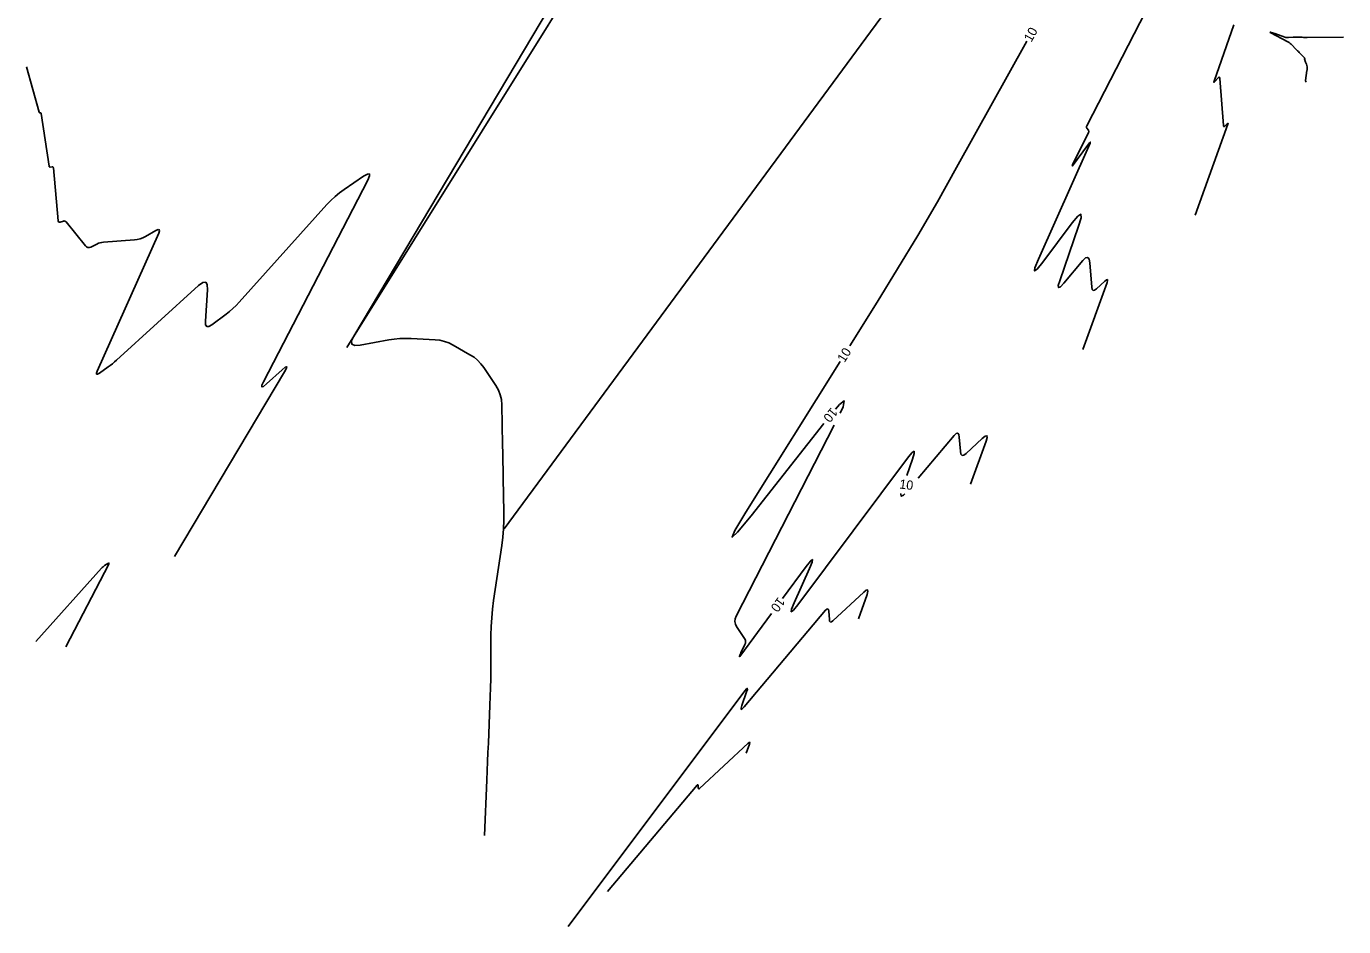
# Model space of a CAD drawing. Extents: x 1797789 to 1803805, y 249066 to 250293.
# Drawn here: x 1797789 to 1798641, y 249066 to 249649 of the extents above; entities that cross this region are included whole.
import ezdxf

# ---------------------------------------------------------------- set-up
doc = ezdxf.new("R2010")
doc.units = 0
doc.layers.add('33', color=7, linetype='Continuous')
doc.layers.add('34', color=7, linetype='Continuous')

msp = doc.modelspace()

# ---------------------------------------------------------------- linework, layer by layer
at = {"layer": '33'}
for points in [[(1798321.84, 249442.04), (1798339.44, 249470.2), (1798352.71, 249491.73), (1798365.7, 249513.42), (1798378.4, 249535.27), (1798390.83, 249557.29), (1798436.35, 249639.15)], [(1798304.84, 249391.7), (1798257.8, 249332.04), (1798249.05, 249321.35), (1798245.59, 249318.17), (1798247.41, 249322.51), (1798254.52, 249334.35), (1798315.48, 249431.87)], [(1798315.5, 249398.47), (1798317.39, 249402.46), (1798318.18, 249406.33), (1798314.99, 249404), (1798312.45, 249400.98)], [(1798271.07, 249268.72), (1798250.6, 249240.92), (1798250.45, 249240.74), (1798250.37, 249240.7), (1798250.36, 249240.79), (1798250.43, 249241.01), (1798250.82, 249242.17), (1798250.92, 249242.46), (1798251.03, 249242.75), (1798251.16, 249243.03), (1798251.29, 249243.31), (1798253.91, 249248.66), (1798254.25, 249249.63), (1798254.33, 249250.59), (1798254.13, 249251.53), (1798253.67, 249252.46), (1798248.5, 249260.3), (1798247.68, 249261.93), (1798247.34, 249263.58), (1798247.5, 249265.26), (1798248.14, 249266.97), (1798311.69, 249390.58)], [(1798399.94, 249352.45), (1798409.98, 249380.38), (1798410.62, 249382.7), (1798410.42, 249383.75), (1798409.38, 249383.52), (1798407.5, 249382.02), (1798397.03, 249372.28), (1798395.53, 249371.2), (1798394.42, 249371.08), (1798393.67, 249371.93), (1798393.31, 249373.74), (1798392.6, 249382.9), (1798392.26, 249384.69), (1798391.59, 249385.46), (1798390.6, 249385.22), (1798389.28, 249383.97), (1798365.98, 249356.32)], [(1798358.73, 249358.11), (1798362.39, 249368.64), (1798363.45, 249372.26), (1798363.35, 249373.71), (1798362.1, 249372.98), (1798359.69, 249370.07), (1798288.07, 249274.34), (1798285.21, 249270.79), (1798283.87, 249269.84), (1798284.06, 249271.47), (1798285.77, 249275.7), (1798295.65, 249297.78), (1798297.37, 249302), (1798297.57, 249303.63), (1798296.25, 249302.65), (1798293.42, 249299.08), (1798278.18, 249278.38)], [(1798357.27, 249346.2), (1798356.38, 249345.27), (1798354.99, 249344.65), (1798354.81, 249346.17), (1798354.91, 249346.51)]]:
    msp.add_lwpolyline(points, dxfattribs=at)
at = {"layer": '34'}
for points in [[(1797996.22, 249440.82), (1798257.93, 249860.06)], [(1798085.37, 249125.11), (1798086.84, 249160.94), (1798087.08, 249166.91), (1798087.33, 249172.88), (1798087.58, 249178.85), (1798087.83, 249184.82), (1798088.85, 249209.38), (1798089.06, 249215.04), (1798089.22, 249220.7), (1798089.33, 249226.35), (1798089.39, 249232.01), (1798089.53, 249254.65), (1798089.67, 249260.3), (1798090, 249265.94), (1798090.53, 249271.56), (1798091.26, 249277.17), (1798096.5, 249312.67), (1798097.19, 249318.08), (1798097.65, 249323.5), (1798097.89, 249328.93), (1798097.9, 249334.38), (1798097.49, 249356.22), (1798097.39, 249361.67), (1798097.28, 249367.11), (1798097.17, 249372.55), (1798097.06, 249377.99), (1798096.53, 249403.87), (1798096.24, 249407.18), (1798095.49, 249410.34), (1798094.29, 249413.37), (1798092.64, 249416.25), (1798084.87, 249427.92), (1798083.01, 249430.4), (1798080.9, 249432.61), (1798078.55, 249434.56), (1798075.95, 249436.24), (1798065.07, 249442.46), (1798062.3, 249443.84), (1798059.43, 249444.88), (1798056.45, 249445.56), (1798053.37, 249445.9), (1798037.83, 249446.73), (1798034.2, 249446.82), (1798030.58, 249446.69), (1798026.98, 249446.35), (1798023.4, 249445.8), (1798004.8, 249442.39), (1798001.33, 249442.17), (1797999.48, 249443.09), (1797999.27, 249445.14), (1798000.68, 249448.32), (1798221.08, 249818.48)], [(1798415.67, 249754.67), (1798098.1, 249323.47)], [(1798472.62, 249439.53), (1798488.19, 249482.87), (1798488.57, 249484.23), (1798488.45, 249484.84), (1798487.84, 249484.71), (1798486.74, 249483.83), (1798481.33, 249478.8), (1798480.13, 249477.93), (1798479.23, 249477.83), (1798478.64, 249478.51), (1798478.34, 249479.97), (1798477.13, 249495.6), (1798476.65, 249498.11), (1798475.71, 249499.19), (1798474.32, 249498.86), (1798472.47, 249497.1), (1798460.23, 249482.58), (1798458.02, 249480.24), (1798456.83, 249479.71), (1798456.68, 249481), (1798457.55, 249484.1), (1798469.81, 249519.34), (1798471.43, 249524.88), (1798471.28, 249527.1), (1798469.37, 249525.98), (1798465.68, 249521.53), (1798446.75, 249496.22), (1798443.05, 249491.64), (1798441.32, 249490.41), (1798441.56, 249492.52), (1798443.77, 249497.97), (1798476.51, 249571.13), (1798477.3, 249573.06), (1798477.39, 249573.8), (1798476.79, 249573.35), (1798475.49, 249571.72), (1798465.75, 249558.49), (1798465.72, 249558.45), (1798465.7, 249558.43), (1798465.69, 249558.46), (1798465.71, 249558.52), (1798465.81, 249558.82), (1798465.84, 249558.89), (1798465.87, 249558.97), (1798465.9, 249559.04), (1798465.93, 249559.11), (1798476.19, 249580.06), (1798476.33, 249580.43), (1798476.35, 249580.8), (1798476.28, 249581.16), (1798476.1, 249581.51), (1798475.18, 249582.92), (1798475, 249583.27), (1798474.93, 249583.63), (1798474.96, 249583.99), (1798475.1, 249584.37), (1798524.74, 249680.93)], [(1798570.16, 249649.7), (1798557.48, 249613.27), (1798557.32, 249612.7), (1798557.35, 249612.46), (1798557.57, 249612.55), (1798557.98, 249612.99), (1798560.01, 249615.39), (1798560.46, 249615.82), (1798560.8, 249615.9), (1798561.02, 249615.64), (1798561.14, 249615.03), (1798563.51, 249584.5), (1798563.6, 249584.07), (1798563.77, 249583.87), (1798564.04, 249583.9), (1798564.39, 249584.16), (1798565.98, 249585.64), (1798566.31, 249585.9), (1798566.49, 249585.94), (1798566.52, 249585.75), (1798566.41, 249585.35), (1798545.3, 249526.6)], [(1798641.32, 249641.65), (1798617.74, 249641.63), (1798616.94, 249641.63), (1798616.15, 249641.63), (1798615.35, 249641.63), (1798614.56, 249641.64), (1798610.91, 249641.66), (1798610.35, 249641.66), (1798609.79, 249641.66), (1798609.23, 249641.65), (1798608.67, 249641.64), (1798605.6, 249641.56), (1798605.46, 249641.55), (1798605.32, 249641.55), (1798605.18, 249641.54), (1798605.04, 249641.54), (1798604.49, 249641.52), (1798604.35, 249641.52), (1798604.22, 249641.53), (1798604.08, 249641.56), (1798603.95, 249641.6), (1798599.16, 249643.21), (1798598.56, 249643.41), (1798597.96, 249643.61), (1798597.36, 249643.81), (1798596.76, 249644.01), (1798594.35, 249644.82), (1798593.9, 249644.96), (1798593.73, 249644.97), (1798593.85, 249644.85), (1798594.26, 249644.61), (1798605.26, 249638.63), (1798605.99, 249638.21), (1798606.67, 249637.73), (1798607.31, 249637.2), (1798607.92, 249636.61), (1798610.27, 249634.19), (1798610.86, 249633.58), (1798611.45, 249632.98), (1798612.03, 249632.37), (1798612.62, 249631.76), (1798616.15, 249628.12), (1798616.15, 249628.11), (1798616.16, 249628.09), (1798616.16, 249628.08), (1798616.15, 249628.07), (1798616.1, 249628.01), (1798616.09, 249628), (1798616.08, 249627.98), (1798616.07, 249627.97), (1798616.06, 249627.95), (1798615.99, 249627.87), (1798615.98, 249627.86), (1798615.97, 249627.84), (1798615.97, 249627.82), (1798615.98, 249627.8), (1798616.72, 249625.61), (1798616.84, 249625.28), (1798616.95, 249624.94), (1798617.07, 249624.6), (1798617.18, 249624.26), (1798617.73, 249622.62), (1798617.78, 249622.42), (1798617.81, 249622.22), (1798617.82, 249622.02), (1798617.81, 249621.81), (1798617.71, 249620.99), (1798617.68, 249620.79), (1798617.65, 249620.58), (1798617.63, 249620.38), (1798617.6, 249620.17), (1798616.65, 249613.61), (1798616.65, 249613.6), (1798616.65, 249613.59), (1798616.66, 249613.58), (1798616.66, 249613.57), (1798616.67, 249613.53), (1798616.68, 249613.5), (1798617, 249612.51)], [(1797884.81, 249305.53), (1797956.01, 249425.13), (1797957.23, 249427.41), (1797957.37, 249428.39), (1797956.44, 249428.06), (1797954.43, 249426.43), (1797944.27, 249417.28), (1797942.24, 249415.66), (1797941.25, 249415.37), (1797941.27, 249416.41), (1797942.33, 249418.78), (1798009.81, 249549.22), (1798010.94, 249551.89), (1798010.85, 249553.19), (1798009.55, 249553.12), (1798007.04, 249551.68), (1797994.57, 249543.2), (1797991.52, 249541), (1797988.63, 249538.62), (1797985.89, 249536.07), (1797983.29, 249533.35), (1797926.54, 249470.15), (1797924.58, 249468.07), (1797922.52, 249466.1), (1797920.37, 249464.23), (1797918.12, 249462.47), (1797908.95, 249455.63), (1797906.96, 249454.5), (1797905.6, 249454.5), (1797904.86, 249455.64), (1797904.73, 249457.93), (1797906.07, 249478.16), (1797905.92, 249481.58), (1797904.9, 249483.19), (1797903, 249482.99), (1797900.24, 249480.97), (1797847.17, 249432.65), (1797845.88, 249431.51), (1797844.54, 249430.41), (1797843.18, 249429.35), (1797841.78, 249428.33), (1797836.1, 249424.36), (1797834.95, 249423.69), (1797834.33, 249423.66), (1797834.24, 249424.27), (1797834.68, 249425.53), (1797874.48, 249514.96), (1797874.95, 249516.39), (1797874.81, 249517.13), (1797874.06, 249517.2), (1797872.68, 249516.59), (1797865.96, 249512.79), (1797864.24, 249511.94), (1797862.47, 249511.29), (1797860.64, 249510.84), (1797858.74, 249510.59), (1797838.7, 249509.02), (1797837.6, 249508.89), (1797836.54, 249508.65), (1797835.5, 249508.31), (1797834.48, 249507.87), (1797830.49, 249505.92), (1797829.52, 249505.6), (1797828.64, 249505.62), (1797827.83, 249505.98), (1797827.09, 249506.68), (1797814.65, 249522.16), (1797814.27, 249522.53), (1797813.85, 249522.74), (1797813.37, 249522.8), (1797812.85, 249522.7), (1797810.69, 249522.01), (1797810.21, 249521.93), (1797809.85, 249522.04), (1797809.61, 249522.33), (1797809.5, 249522.8), (1797806.37, 249557.2), (1797806.3, 249557.49), (1797806.16, 249557.69), (1797805.94, 249557.8), (1797805.64, 249557.81), (1797804.29, 249557.68), (1797803.99, 249557.69), (1797803.77, 249557.79), (1797803.61, 249557.99), (1797803.52, 249558.28), (1797798.49, 249592.29), (1797798.45, 249592.43), (1797798.37, 249592.54), (1797798.26, 249592.62), (1797798.12, 249592.66), (1797797.47, 249592.76), (1797797.32, 249592.81), (1797797.21, 249592.88), (1797797.12, 249592.99), (1797797.06, 249593.13), (1797788.85, 249622.45)], [(1797814.41, 249247.16), (1797842.12, 249300.74), (1797842.32, 249301.21), (1797842.3, 249301.43), (1797842.08, 249301.42), (1797841.64, 249301.17), (1797839.49, 249299.7), (1797838.96, 249299.32), (1797838.46, 249298.91), (1797837.99, 249298.47), (1797837.54, 249298), (1797794.99, 249250.61)], [(1798139.58, 249066.07), (1798253.71, 249218.62), (1798254.84, 249219.98), (1798255.42, 249220.32), (1798255.47, 249219.64), (1798254.97, 249217.94), (1798251.9, 249209.11), (1798251.42, 249207.4), (1798251.5, 249206.69), (1798252.15, 249206.98), (1798253.38, 249208.27), (1798306.09, 249270.84), (1798306.87, 249271.58), (1798307.46, 249271.72), (1798307.86, 249271.26), (1798308.06, 249270.2), (1798308.49, 249264.75), (1798308.7, 249263.67), (1798309.15, 249263.17), (1798309.81, 249263.24), (1798310.7, 249263.89), (1798330.71, 249282.49), (1798332.37, 249283.82), (1798333.29, 249284.02), (1798333.46, 249283.09), (1798332.9, 249281.05), (1798327.27, 249265.38)], [(1798254.59, 249178.31), (1798256.73, 249184.25), (1798256.94, 249185.03), (1798256.87, 249185.38), (1798256.53, 249185.3), (1798255.9, 249184.8), (1798224.37, 249155.49), (1798224.09, 249155.28), (1798223.88, 249155.26), (1798223.73, 249155.42), (1798223.66, 249155.76), (1798223.53, 249157.5), (1798223.47, 249157.84), (1798223.34, 249157.99), (1798223.15, 249157.94), (1798222.9, 249157.7), (1798164.84, 249088.8)]]:
    msp.add_lwpolyline(points, dxfattribs=at)

# ---------------------------------------------------------------- texts
at = {"layer": '33'}
for rotation, p in [(60.922, (1798439.22, 249638.12)), (57.99031, (1798318.29, 249430.7)), (230.64913, (1798309.82, 249402.5)), (352.68373, (1798353.54, 249349.71)), (233.63298, (1798275.47, 249279.76))]:
    msp.add_text('10', height=6, rotation=rotation, dxfattribs=at).set_placement(p)

doc.saveas('drawing.dxf')
